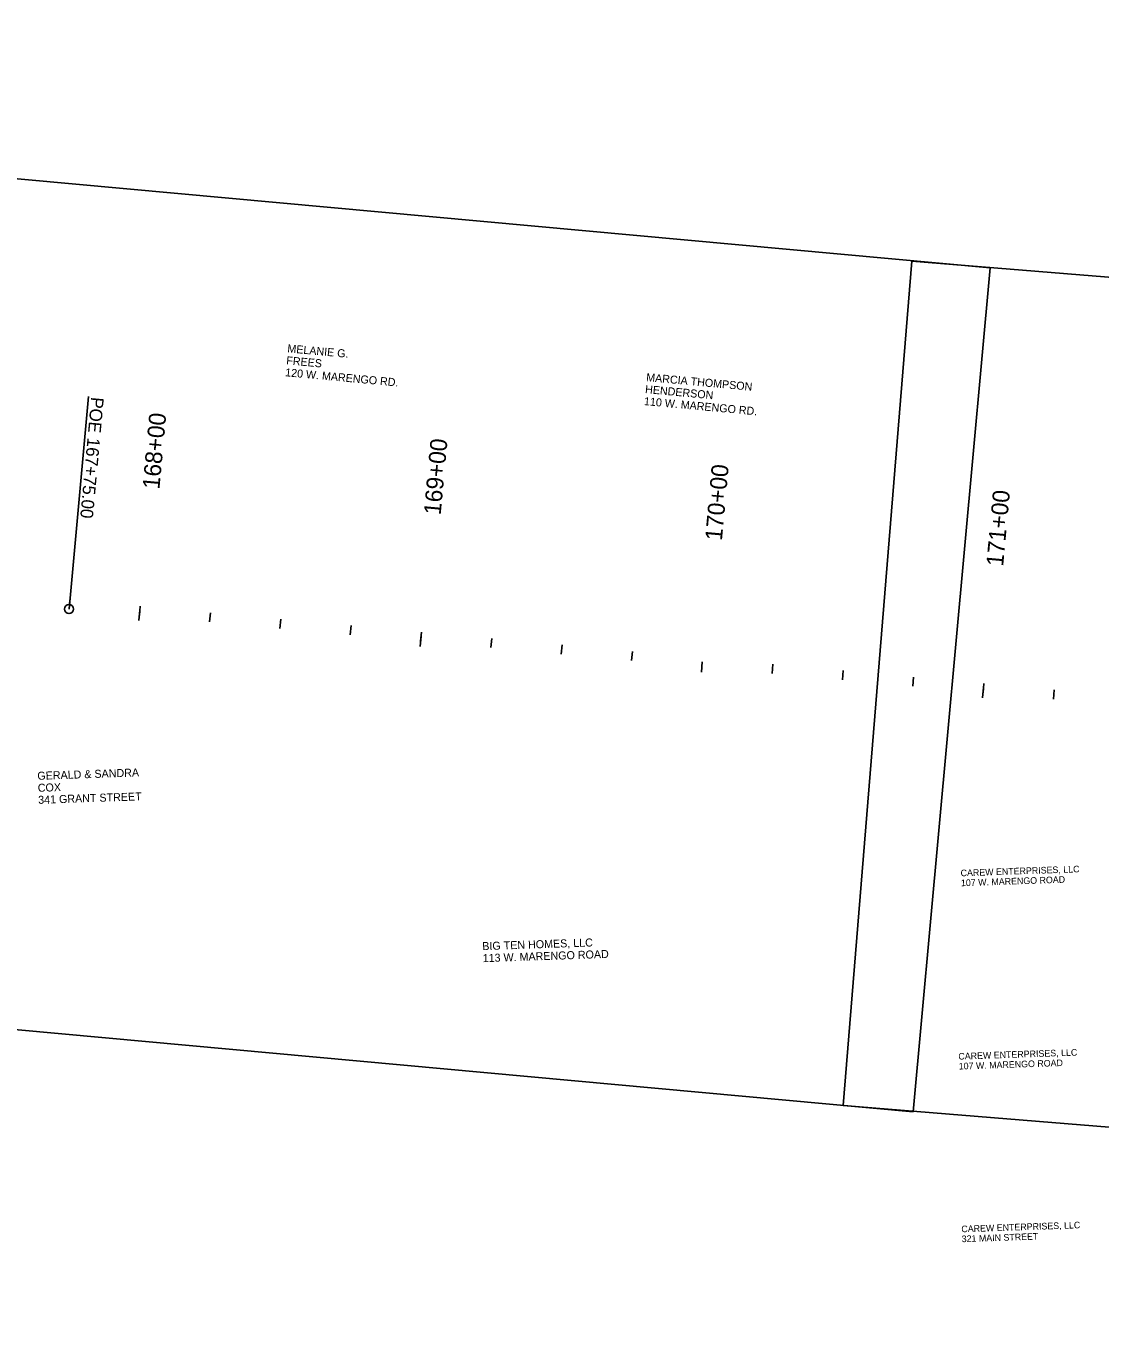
# Model space of a CAD drawing. Extents: x 20499788 to 20505371, y 7953467 to 7954209.
# Drawn here: x 20500472.8 to 20500853.2, y 7953750 to 7954208.6 of the extents above; entities that cross this region are included whole.
import ezdxf

# ---------------------------------------------------------------- set-up
doc = ezdxf.new("R2010")
doc.units = 0
for name, color, linetype in [('NamedBoundary', 7, 'Continuous'), ('Text', 7, 'Continuous'), ('TextAlignment', 7, 'Continuous'), ('TextAlignmentLrg', 7, 'Continuous'), ('TextAlignmentSml', 7, 'Continuous')]:
    doc.layers.add(name, color=color, linetype=linetype)

msp = doc.modelspace()

# ---------------------------------------------------------------- linework, layer by layer
at = {"layer": 'NamedBoundary'}
for points in [[(20499877.7, 7954208.56), (20499850.36, 7953909.81), (20500786.95, 7953824.1), (20500814.29, 7954122.85)], [(20500786.55, 7954125.26), (20500762.22, 7953826.25), (20501699.61, 7953749.96), (20501723.94, 7954048.98)]]:
    msp.add_lwpolyline(points, close=True, dxfattribs=at)
at = {"layer": 'TextAlignment'}
for p in [(20500488.09, 7954002.08), (20500494.98, 7954077.36)]:
    msp.add_line(p, (20500494.98, 7954077.36), dxfattribs=at)
msp.add_circle((20500488.09, 7954002.08), 1.6, dxfattribs=at)
at = {"layer": 'TextAlignmentLrg'}
for p, q in [((20500512.99, 7953999.8), (20500513.29, 7954003.06)), ((20500612.57, 7953990.69), (20500612.87, 7953993.95)), ((20500712.32, 7953983.4), (20500711.99, 7953979.74)), ((20500811.74, 7953972.46), (20500812.04, 7953975.72))]:
    msp.add_line(p, q, dxfattribs=at)
at = {"layer": 'TextAlignmentSml'}
for p, q in [((20500488.09, 7954002.08), (20500488.39, 7954005.34)), ((20500513.15, 7954001.63), (20500512.82, 7953997.97)), ((20500537.88, 7953997.52), (20500538.18, 7954000.78)), ((20500562.78, 7953995.24), (20500563.08, 7953998.5)), ((20500587.68, 7953992.96), (20500587.97, 7953996.23)), ((20500612.74, 7953992.51), (20500612.4, 7953988.86)), ((20500637.47, 7953988.41), (20500637.77, 7953991.67)), ((20500662.36, 7953986.13), (20500662.66, 7953989.39)), ((20500687.26, 7953983.85), (20500687.56, 7953987.11)), ((20500712.32, 7953983.4), (20500711.99, 7953979.74)), ((20500737.05, 7953979.29), (20500737.35, 7953982.56)), ((20500761.95, 7953977.02), (20500762.25, 7953980.28)), ((20500786.84, 7953974.74), (20500787.14, 7953978)), ((20500811.91, 7953974.29), (20500811.57, 7953970.63)), ((20500836.64, 7953970.18), (20500836.93, 7953973.44))]:
    msp.add_line(p, q, dxfattribs=at)

# ---------------------------------------------------------------- texts
at = {"layer": 'Text'}
for s, height, rotation, p in [('MELANIE G.', 2.835, 354.7645, (20500565.31, 7954093)), ('FREES', 2.835, 354.7645, (20500564.92, 7954088.76)), ('120 W. MARENGO RD.', 2.8346, 354.7645, (20500564.54, 7954084.53)), ('MARCIA THOMPSON', 2.8346, 354.7645, (20500692.36, 7954082.8)), ('HENDERSON', 2.835, 354.7645, (20500691.97, 7954078.57)), ('110 W. MARENGO RD.', 2.8346, 354.7645, (20500691.58, 7954074.33)), ('GERALD & SANDRA', 2.8346, 1.9645, (20500476.92, 7953941.6)), ('COX', 2.835, 1.9645, (20500477.07, 7953937.35)), ('341 GRANT STREET', 2.8346, 1.9645, (20500477.21, 7953933.1)), ('CAREW ENTERPRISES, LLC', 2.3424, 1.9645, (20500803.82, 7953907.44)), ('107 W. MARENGO ROAD', 2.3424, 1.9645, (20500803.94, 7953903.93)), ('BIG TEN HOMES, LLC', 2.8346, 1.9645, (20500634.46, 7953881.29)), ('113 W. MARENGO ROAD', 2.8346, 1.9645, (20500634.61, 7953877.04)), ('CAREW ENTERPRISES, LLC', 2.3424, 1.9645, (20500803.03, 7953842.53)), ('107 W. MARENGO ROAD', 2.3424, 1.9645, (20500803.16, 7953839.02)), ('CAREW ENTERPRISES, LLC', 2.3424, 1.9645, (20500804.09, 7953781.4)), ('321 MAIN STREET', 2.3424, 1.9645, (20500804.21, 7953777.89))]:
    msp.add_text(s, height=height, rotation=rotation, dxfattribs=at).set_placement(p)
at = {"layer": 'TextAlignment'}
for s, p in [('POE ', (20500495.96, 7954077.27)), ('167+75.00', (20500494.65, 7954062.89))]:
    msp.add_text(s, height=4.5, rotation=264.7714, dxfattribs=at).set_placement(p)
at = {"layer": 'TextAlignmentLrg'}
msp.add_text('170+00', height=6.012, rotation=84.7714, dxfattribs=at).set_placement((20500719.25, 7954026.11))
at = {"layer": 'TextAlignmentSml'}
for s, p in [('168+00', (20500520.08, 7954044.34)), ('169+00', (20500619.67, 7954035.22)), ('170+00', (20500719.25, 7954026.11)), ('171+00', (20500818.83, 7954017))]:
    msp.add_text(s, height=6.012, rotation=84.7714, dxfattribs=at).set_placement(p)

doc.saveas('drawing.dxf')
